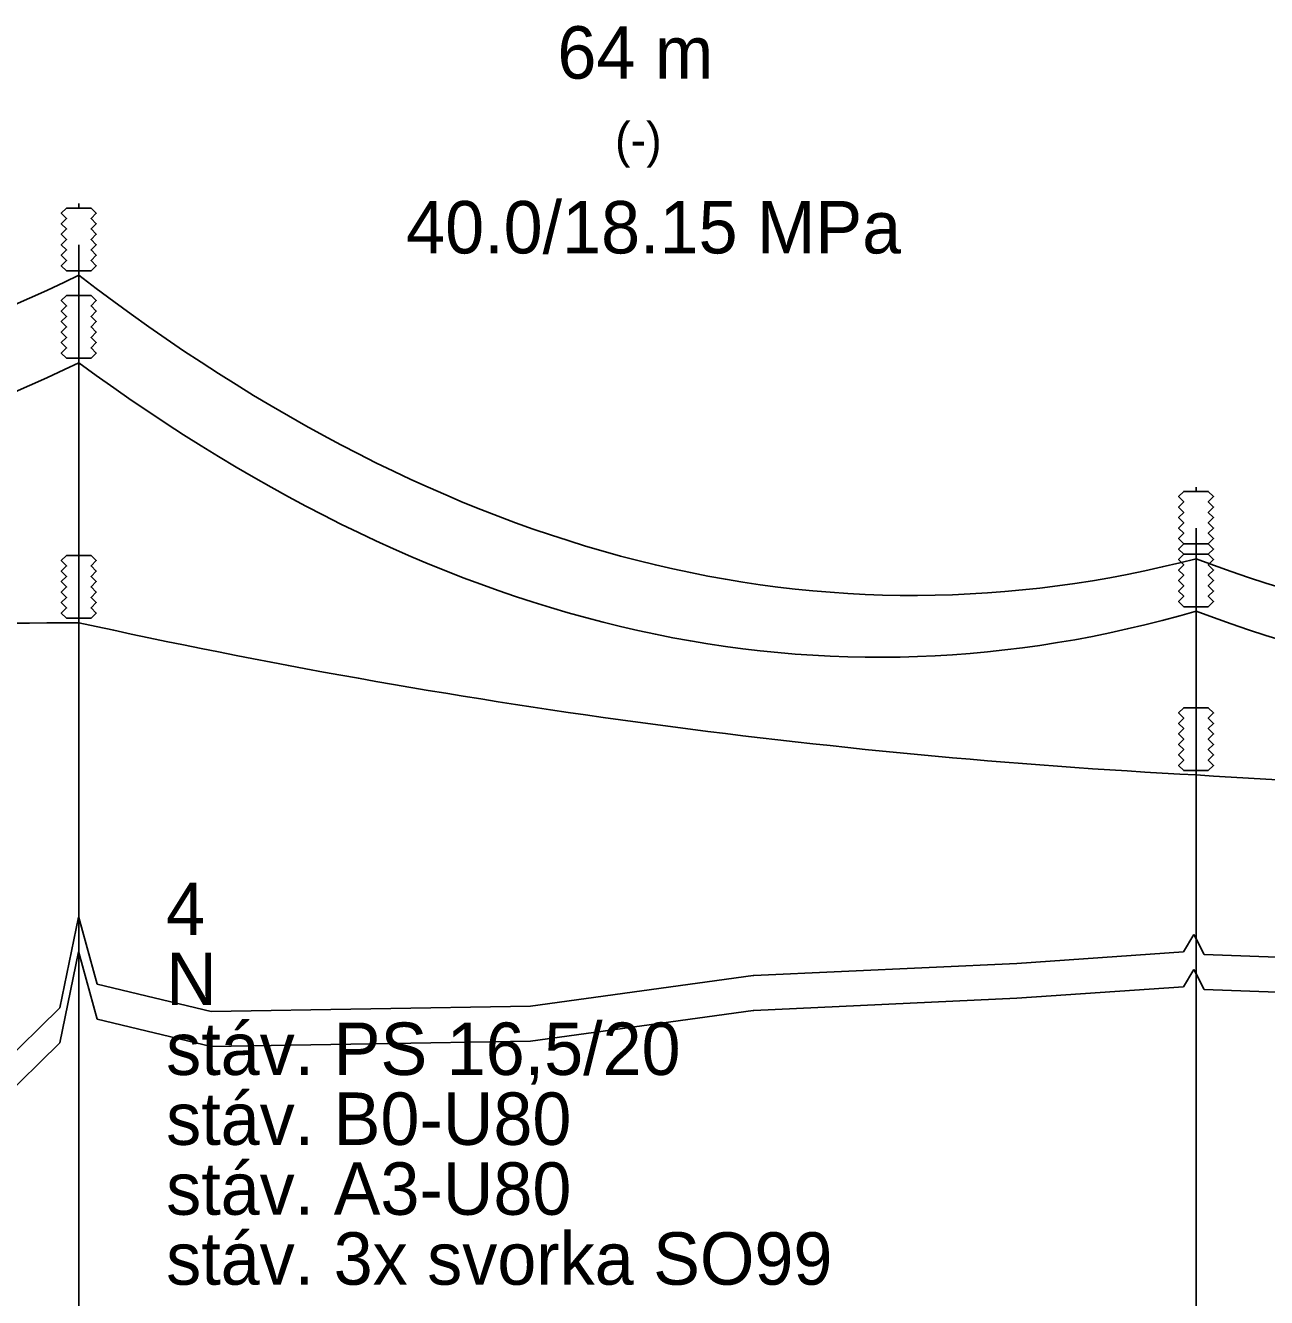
# Model space of a CAD drawing. Extents: x -21 to 628, y 809 to 990.
# Drawn here: x 388.6 to 459.7, y 910 to 982.8 of the extents above; entities that cross this region are included whole.
import ezdxf

# ---------------------------------------------------------------- set-up
doc = ezdxf.new("R2010")
doc.units = 0
for name, color, linetype in [('Vrstva 11', 7, 'Continuous'), ('Vrstva 12', 7, 'Continuous'), ('Vrstva 13', 7, 'Continuous'), ('Vrstva 14', 7, 'Continuous'), ('Vrstva 15', 7, 'Continuous'), ('Vrstva 29', 7, 'Continuous'), ('Vrstva 3', 7, 'Continuous')]:
    doc.layers.add(name, color=color, linetype=linetype)

msp = doc.modelspace()

# ---------------------------------------------------------------- linework, layer by layer
at = {"layer": 'Vrstva 11'}
for points in [[(387.861, 966.715), (388.861, 967.15), (389.861, 967.602), (390.861, 968.069), (391.681, 968.464)], [(391.681, 968.464), (392.681, 967.704), (393.681, 966.961), (394.681, 966.235), (395.681, 965.524), (396.681, 964.829), (397.681, 964.15), (398.681, 963.487), (399.681, 962.841), (400.681, 962.21), (401.681, 961.596), (402.681, 960.997), (403.681, 960.415), (404.681, 959.849), (405.681, 959.298), (406.681, 958.764), (407.681, 958.246), (408.681, 957.744), (409.681, 957.258), (410.681, 956.788), (411.681, 956.334), (412.681, 955.897), (413.681, 955.475), (414.681, 955.069), (415.681, 954.68), (416.681, 954.306), (417.681, 953.949), (418.681, 953.607), (419.681, 953.282), (420.681, 952.973), (421.681, 952.679), (422.681, 952.402), (423.681, 952.141), (424.681, 951.896), (425.681, 951.667), (426.681, 951.454), (427.681, 951.258), (428.681, 951.077), (429.681, 950.912), (430.681, 950.764), (431.681, 950.631), (432.681, 950.514), (433.681, 950.414), (434.681, 950.33), (435.681, 950.261), (436.681, 950.209), (437.681, 950.173), (438.681, 950.153), (439.681, 950.149), (440.681, 950.161), (441.681, 950.189), (442.681, 950.233), (443.681, 950.293), (444.681, 950.37), (445.681, 950.462), (446.681, 950.57), (447.681, 950.695), (448.681, 950.835), (449.681, 950.992), (450.681, 951.165), (451.681, 951.353), (452.681, 951.558), (453.681, 951.779), (454.681, 952.016), (455.616, 952.252)], [(387.861, 961.715), (388.861, 962.15), (389.861, 962.602), (390.861, 963.069), (391.681, 963.464)], [(387.861, 961.715), (388.861, 962.15), (389.861, 962.602), (390.861, 963.069), (391.681, 963.464)], [(391.681, 963.464), (392.681, 962.736), (393.681, 962.024), (394.681, 961.328), (395.681, 960.649), (396.681, 959.985), (397.681, 959.338), (398.681, 958.706), (399.681, 958.091), (400.681, 957.492), (401.681, 956.909), (402.681, 956.341), (403.681, 955.79), (404.681, 955.255), (405.681, 954.736), (406.681, 954.233), (407.681, 953.747), (408.681, 953.276), (409.681, 952.821), (410.681, 952.383), (411.681, 951.96), (412.681, 951.554), (413.681, 951.163), (414.681, 950.789), (415.681, 950.43), (416.681, 950.088), (417.681, 949.762), (418.681, 949.452), (419.681, 949.158), (420.681, 948.88), (421.681, 948.618), (422.681, 948.372), (423.681, 948.142), (424.681, 947.929), (425.681, 947.731), (426.681, 947.549), (427.681, 947.384), (428.681, 947.234), (429.681, 947.101), (430.681, 946.984), (431.681, 946.882), (432.681, 946.797), (433.681, 946.728), (434.681, 946.675), (435.681, 946.638), (436.681, 946.617), (437.681, 946.612), (438.681, 946.623), (439.681, 946.65), (440.681, 946.694), (441.681, 946.753), (442.681, 946.829), (443.681, 946.92), (444.681, 947.028), (445.681, 947.151), (446.681, 947.291), (447.681, 947.447), (448.681, 947.618), (449.681, 947.806), (450.681, 948.01), (451.681, 948.23), (452.681, 948.466), (453.681, 948.719), (454.681, 948.987), (455.616, 949.252)], [(391.681, 963.464), (392.681, 962.736), (393.681, 962.024), (394.681, 961.328), (395.681, 960.649), (396.681, 959.985), (397.681, 959.338), (398.681, 958.706), (399.681, 958.091), (400.681, 957.492), (401.681, 956.909), (402.681, 956.341), (403.681, 955.79), (404.681, 955.255), (405.681, 954.736), (406.681, 954.233), (407.681, 953.747), (408.681, 953.276), (409.681, 952.821), (410.681, 952.383), (411.681, 951.96), (412.681, 951.554), (413.681, 951.163), (414.681, 950.789), (415.681, 950.43), (416.681, 950.088), (417.681, 949.762), (418.681, 949.452), (419.681, 949.158), (420.681, 948.88), (421.681, 948.618), (422.681, 948.372), (423.681, 948.142), (424.681, 947.929), (425.681, 947.731), (426.681, 947.549), (427.681, 947.384), (428.681, 947.234), (429.681, 947.101), (430.681, 946.984), (431.681, 946.882), (432.681, 946.797), (433.681, 946.728), (434.681, 946.675), (435.681, 946.638), (436.681, 946.617), (437.681, 946.612), (438.681, 946.623), (439.681, 946.65), (440.681, 946.694), (441.681, 946.753), (442.681, 946.829), (443.681, 946.92), (444.681, 947.028), (445.681, 947.151), (446.681, 947.291), (447.681, 947.447), (448.681, 947.618), (449.681, 947.806), (450.681, 948.01), (451.681, 948.23), (452.681, 948.466), (453.681, 948.719), (454.681, 948.987), (455.616, 949.252)], [(455.616, 952.252), (456.616, 951.88), (457.616, 951.524), (458.616, 951.183), (459.616, 950.859), (460.616, 950.551)], [(455.616, 949.252), (456.616, 948.88), (457.616, 948.524), (458.616, 948.183), (459.616, 947.859), (460.616, 947.551)], [(455.616, 949.252), (456.616, 948.88), (457.616, 948.524), (458.616, 948.183), (459.616, 947.859), (460.616, 947.551)], [(387.861, 948.568), (388.861, 948.569), (389.861, 948.574), (390.861, 948.581), (391.681, 948.589)], [(391.681, 948.589), (392.681, 948.37), (393.681, 948.154), (394.681, 947.941), (395.681, 947.73), (396.681, 947.522), (397.681, 947.317), (398.681, 947.114), (399.681, 946.914), (400.681, 946.716), (401.681, 946.522), (402.681, 946.329), (403.681, 946.139), (404.681, 945.952), (405.681, 945.768), (406.681, 945.586), (407.681, 945.407), (408.681, 945.23), (409.681, 945.056), (410.681, 944.885), (411.681, 944.716), (412.681, 944.55), (413.681, 944.386), (414.681, 944.225), (415.681, 944.067), (416.681, 943.911), (417.681, 943.758), (418.681, 943.607), (419.681, 943.459), (420.681, 943.314), (421.681, 943.171), (422.681, 943.031), (423.681, 942.894), (424.681, 942.759), (425.681, 942.627), (426.681, 942.497), (427.681, 942.37), (428.681, 942.246), (429.681, 942.124), (430.681, 942.005), (431.681, 941.888), (432.681, 941.774), (433.681, 941.663), (434.681, 941.554), (435.681, 941.448), (436.681, 941.344), (437.681, 941.243), (438.681, 941.145), (439.681, 941.049), (440.681, 940.956), (441.681, 940.866), (442.681, 940.778), (443.681, 940.693), (444.681, 940.61), (445.681, 940.53), (446.681, 940.453), (447.681, 940.378), (448.681, 940.306), (449.681, 940.236), (450.681, 940.169), (451.681, 940.105), (452.681, 940.043), (453.681, 939.984), (454.681, 939.928), (455.616, 939.877)], [(455.616, 939.877), (456.616, 939.814), (457.616, 939.754), (458.616, 939.697), (459.616, 939.642), (460.616, 939.589)]]:
    msp.add_lwpolyline(points, dxfattribs=at)
at = {"layer": 'Vrstva 14'}
for p, q in [((391.681, 901.714), (391.681, 970.214)), ((455.616, 900.502), (455.616, 954.002))]:
    msp.add_line(p, q, dxfattribs=at)
at = {"layer": 'Vrstva 29'}
for points in [[(391.681, 972.314), (391.681, 972.564)], [(391.681, 968.464), (391.681, 968.714)], [(391.681, 967.314), (391.681, 967.564)], [(391.681, 967.314), (391.681, 967.564)], [(391.681, 963.464), (391.681, 963.714)], [(391.681, 963.464), (391.681, 963.714)], [(455.616, 956.102), (455.616, 956.352)], [(391.681, 952.439), (391.681, 952.689)], [(391.681, 952.439), (391.681, 952.689)], [(455.616, 953.102), (455.616, 953.352)], [(455.616, 953.102), (455.616, 953.352)], [(455.616, 952.252), (455.616, 952.502)], [(455.616, 949.252), (455.616, 949.502)], [(455.616, 949.252), (455.616, 949.502)], [(391.681, 948.589), (391.681, 948.839)], [(391.681, 948.589), (391.681, 948.839)], [(455.616, 943.727), (455.616, 943.977)], [(455.616, 939.877), (455.616, 940.127)]]:
    msp.add_lwpolyline(points, dxfattribs=at)
for points in [[(392.381, 968.714), (390.981, 968.714), (390.681, 969.014), (390.981, 969.314), (390.681, 969.614), (390.981, 969.914), (390.681, 970.214), (390.981, 970.514), (390.681, 970.814), (390.981, 971.114), (390.681, 971.414), (390.981, 971.714), (390.681, 972.014), (390.981, 972.314), (392.381, 972.314), (392.681, 972.014), (392.381, 971.714), (392.681, 971.414), (392.381, 971.114), (392.681, 970.814), (392.381, 970.514), (392.681, 970.214), (392.381, 969.914), (392.681, 969.614), (392.381, 969.314), (392.681, 969.014)], [(392.381, 963.714), (390.981, 963.714), (390.681, 964.014), (390.981, 964.314), (390.681, 964.614), (390.981, 964.914), (390.681, 965.214), (390.981, 965.514), (390.681, 965.814), (390.981, 966.114), (390.681, 966.414), (390.981, 966.714), (390.681, 967.014), (390.981, 967.314), (392.381, 967.314), (392.681, 967.014), (392.381, 966.714), (392.681, 966.414), (392.381, 966.114), (392.681, 965.814), (392.381, 965.514), (392.681, 965.214), (392.381, 964.914), (392.681, 964.614), (392.381, 964.314), (392.681, 964.014)], [(392.381, 963.714), (390.981, 963.714), (390.681, 964.014), (390.981, 964.314), (390.681, 964.614), (390.981, 964.914), (390.681, 965.214), (390.981, 965.514), (390.681, 965.814), (390.981, 966.114), (390.681, 966.414), (390.981, 966.714), (390.681, 967.014), (390.981, 967.314), (392.381, 967.314), (392.681, 967.014), (392.381, 966.714), (392.681, 966.414), (392.381, 966.114), (392.681, 965.814), (392.381, 965.514), (392.681, 965.214), (392.381, 964.914), (392.681, 964.614), (392.381, 964.314), (392.681, 964.014)], [(456.316, 952.502), (454.916, 952.502), (454.616, 952.802), (454.916, 953.102), (454.616, 953.402), (454.916, 953.702), (454.616, 954.002), (454.916, 954.302), (454.616, 954.602), (454.916, 954.902), (454.616, 955.202), (454.916, 955.502), (454.616, 955.802), (454.916, 956.102), (456.316, 956.102), (456.616, 955.802), (456.316, 955.502), (456.616, 955.202), (456.316, 954.902), (456.616, 954.602), (456.316, 954.302), (456.616, 954.002), (456.316, 953.702), (456.616, 953.402), (456.316, 953.102), (456.616, 952.802)], [(456.316, 949.502), (454.916, 949.502), (454.616, 949.802), (454.916, 950.102), (454.616, 950.402), (454.916, 950.702), (454.616, 951.002), (454.916, 951.302), (454.616, 951.602), (454.916, 951.902), (454.616, 952.202), (454.916, 952.502), (454.616, 952.802), (454.916, 953.102), (456.316, 953.102), (456.616, 952.802), (456.316, 952.502), (456.616, 952.202), (456.316, 951.902), (456.616, 951.602), (456.316, 951.302), (456.616, 951.002), (456.316, 950.702), (456.616, 950.402), (456.316, 950.102), (456.616, 949.802)], [(456.316, 949.502), (454.916, 949.502), (454.616, 949.802), (454.916, 950.102), (454.616, 950.402), (454.916, 950.702), (454.616, 951.002), (454.916, 951.302), (454.616, 951.602), (454.916, 951.902), (454.616, 952.202), (454.916, 952.502), (454.616, 952.802), (454.916, 953.102), (456.316, 953.102), (456.616, 952.802), (456.316, 952.502), (456.616, 952.202), (456.316, 951.902), (456.616, 951.602), (456.316, 951.302), (456.616, 951.002), (456.316, 950.702), (456.616, 950.402), (456.316, 950.102), (456.616, 949.802)], [(392.381, 948.839), (390.981, 948.839), (390.681, 949.139), (390.981, 949.439), (390.681, 949.739), (390.981, 950.039), (390.681, 950.339), (390.981, 950.639), (390.681, 950.939), (390.981, 951.239), (390.681, 951.539), (390.981, 951.839), (390.681, 952.139), (390.981, 952.439), (392.381, 952.439), (392.681, 952.139), (392.381, 951.839), (392.681, 951.539), (392.381, 951.239), (392.681, 950.939), (392.381, 950.639), (392.681, 950.339), (392.381, 950.039), (392.681, 949.739), (392.381, 949.439), (392.681, 949.139)], [(392.381, 948.839), (390.981, 948.839), (390.681, 949.139), (390.981, 949.439), (390.681, 949.739), (390.981, 950.039), (390.681, 950.339), (390.981, 950.639), (390.681, 950.939), (390.981, 951.239), (390.681, 951.539), (390.981, 951.839), (390.681, 952.139), (390.981, 952.439), (392.381, 952.439), (392.681, 952.139), (392.381, 951.839), (392.681, 951.539), (392.381, 951.239), (392.681, 950.939), (392.381, 950.639), (392.681, 950.339), (392.381, 950.039), (392.681, 949.739), (392.381, 949.439), (392.681, 949.139)], [(456.316, 940.127), (454.916, 940.127), (454.616, 940.427), (454.916, 940.727), (454.616, 941.027), (454.916, 941.327), (454.616, 941.627), (454.916, 941.927), (454.616, 942.227), (454.916, 942.527), (454.616, 942.827), (454.916, 943.127), (454.616, 943.427), (454.916, 943.727), (456.316, 943.727), (456.616, 943.427), (456.316, 943.127), (456.616, 942.827), (456.316, 942.527), (456.616, 942.227), (456.316, 941.927), (456.616, 941.627), (456.316, 941.327), (456.616, 941.027), (456.316, 940.727), (456.616, 940.427)]]:
    msp.add_lwpolyline(points, close=True, dxfattribs=at)
at = {"layer": 'Vrstva 3'}
for p, q in [((390.605, 926.55), (391.673, 931.75)), ((391.673, 931.75), (391.681, 931.722)), ((391.681, 931.722), (392.741, 927.9)), ((454.898, 929.75), (455.491, 930.75)), ((455.491, 930.75), (455.616, 930.502)), ((455.616, 930.502), (456.073, 929.6)), ((390.605, 924.55), (391.673, 929.75)), ((390.605, 924.55), (391.673, 929.75)), ((390.605, 924.55), (391.673, 929.75)), ((391.673, 929.75), (391.681, 929.722)), ((391.673, 929.75), (391.681, 929.722)), ((391.673, 929.75), (391.681, 929.722)), ((391.681, 929.722), (392.741, 925.9)), ((391.681, 929.722), (392.741, 925.9)), ((391.681, 929.722), (392.741, 925.9)), ((445.354, 929.1), (454.898, 929.75)), ((456.073, 929.6), (467.066, 929.2)), ((430.311, 928.4), (445.354, 929.1)), ((454.898, 927.75), (455.491, 928.75)), ((454.898, 927.75), (455.491, 928.75)), ((454.898, 927.75), (455.491, 928.75)), ((455.491, 928.75), (455.616, 928.502)), ((455.491, 928.75), (455.616, 928.502)), ((455.491, 928.75), (455.616, 928.502)), ((417.521, 926.65), (430.264, 928.4)), ((430.264, 928.4), (430.311, 928.4)), ((455.616, 928.502), (456.073, 927.6)), ((455.616, 928.502), (456.073, 927.6)), ((455.616, 928.502), (456.073, 927.6)), ((392.741, 927.9), (399.261, 926.35)), ((445.354, 927.1), (454.898, 927.75)), ((445.354, 927.1), (454.898, 927.75)), ((445.354, 927.1), (454.898, 927.75)), ((456.073, 927.6), (467.066, 927.2)), ((456.073, 927.6), (467.066, 927.2)), ((456.073, 927.6), (467.066, 927.2)), ((387.181, 923.2), (390.605, 926.55)), ((399.261, 926.35), (417.521, 926.65)), ((430.311, 926.4), (445.354, 927.1)), ((430.311, 926.4), (445.354, 927.1)), ((430.311, 926.4), (445.354, 927.1)), ((392.741, 925.9), (399.261, 924.35)), ((392.741, 925.9), (399.261, 924.35)), ((392.741, 925.9), (399.261, 924.35)), ((417.521, 924.65), (430.264, 926.4)), ((417.521, 924.65), (430.264, 926.4)), ((417.521, 924.65), (430.264, 926.4)), ((430.264, 926.4), (430.311, 926.4)), ((430.264, 926.4), (430.311, 926.4)), ((430.264, 926.4), (430.311, 926.4)), ((387.181, 921.2), (390.605, 924.55)), ((387.181, 921.2), (390.605, 924.55)), ((387.181, 921.2), (390.605, 924.55)), ((399.261, 924.35), (417.521, 924.65)), ((399.261, 924.35), (417.521, 924.65)), ((399.261, 924.35), (417.521, 924.65))]:
    msp.add_line(p, q, dxfattribs=at)

# ---------------------------------------------------------------- texts
at = {"layer": 'Vrstva 12'}
msp.add_text('40.0/18.15 MPa', height=3, dxfattribs=at).set_placement((410.416, 969.714))
at = {"layer": 'Vrstva 13'}
for s, height, p in [('64 m', 3, (419.07, 979.714)), ('(-)', 2, (422.367, 975.214))]:
    msp.add_text(s, height=height, dxfattribs=at).set_placement(p)
at = {"layer": 'Vrstva 15'}
for s, p in [('4', (396.681, 930.714)), ('N', (396.681, 926.714)), ('stáv. PS 16,5/20', (396.681, 922.714)), ('stáv. B0-U80', (396.681, 918.714)), ('stáv. A3-U80', (396.681, 914.714)), ('stáv. 3x svorka SO99', (396.681, 910.714))]:
    msp.add_text(s, height=3, dxfattribs=at).set_placement(p)

doc.saveas('drawing.dxf')
